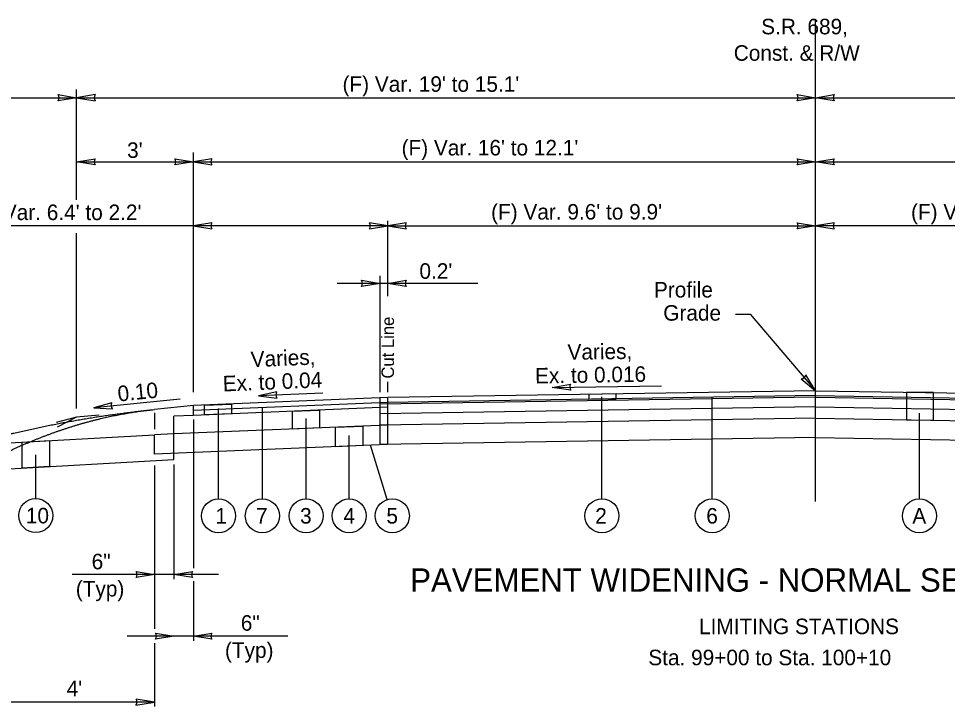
# Model space of a CAD drawing. Extents: x -219 to 803, y -225 to 180.
# Drawn here: x 42.76 to 90.53, y 54.8 to 90.2 of the extents above; entities that cross this region are included whole.
import ezdxf

# ---------------------------------------------------------------- set-up
doc = ezdxf.new("R2010")
doc.units = 0
for name, color, linetype in [('Level 16', 7, 'Continuous'), ('SH_Data', 7, 'Continuous'), ('XS_X_Pavt', 7, 'Continuous')]:
    doc.layers.add(name, color=color, linetype=linetype)

msp = doc.modelspace()

# ---------------------------------------------------------------- linework, layer by layer
at = {"layer": 'Level 16'}
for p, q in [((83.75, 65.34), (83.75, 90.095)), ((45.75, 80.865), (45.75, 86.556)), ((29.75, 86.128), (45.75, 86.128)), ((44.8, 86.286), (45.75, 86.128)), ((45.75, 86.128), (44.803, 85.97)), ((46.7, 86.286), (45.75, 86.128)), ((45.75, 86.128), (83.75, 86.128)), ((45.75, 86.128), (46.697, 85.97)), ((82.8, 86.286), (83.75, 86.128)), ((83.75, 86.128), (82.803, 85.97)), ((83.75, 86.128), (84.697, 86.286)), ((83.75, 86.128), (121.75, 86.128)), ((84.7, 85.97), (83.75, 86.128)), ((84.697, 86.286), (84.697, 86.286)), ((44.803, 85.97), (44.803, 85.97)), ((46.697, 85.97), (46.697, 85.97)), ((82.803, 85.97), (82.803, 85.97)), ((51.75, 70.976), (51.75, 83.314)), ((45.75, 82.828), (46.696, 82.986)), ((46.7, 82.67), (45.75, 82.828)), ((45.75, 82.828), (51.75, 82.828)), ((46.696, 82.986), (46.696, 82.986)), ((50.8, 82.986), (51.75, 82.828)), ((51.75, 82.828), (50.803, 82.67)), ((50.803, 82.67), (50.803, 82.67)), ((52.7, 82.986), (51.75, 82.828)), ((51.75, 82.828), (83.75, 82.828)), ((51.75, 82.828), (52.697, 82.67)), ((52.697, 82.67), (52.697, 82.67)), ((82.8, 82.986), (83.75, 82.828)), ((83.75, 82.828), (82.803, 82.67)), ((82.803, 82.67), (82.803, 82.67)), ((83.75, 82.828), (84.697, 82.986)), ((83.75, 82.828), (115.75, 82.828)), ((84.7, 82.67), (83.75, 82.828)), ((84.697, 82.986), (84.697, 82.986)), ((61.75, 75.906), (61.75, 79.792)), ((51.75, 79.528), (39.562, 79.528)), ((52.7, 79.686), (51.75, 79.528)), ((51.75, 79.528), (52.697, 79.37)), ((61.75, 79.528), (51.75, 79.528)), ((52.697, 79.37), (52.697, 79.37)), ((60.8, 79.37), (61.75, 79.528)), ((61.75, 79.528), (60.804, 79.686)), ((60.804, 79.686), (60.804, 79.686)), ((62.7, 79.686), (61.75, 79.528)), ((61.75, 79.528), (83.75, 79.528)), ((61.75, 79.528), (62.697, 79.37)), ((62.697, 79.37), (62.697, 79.37)), ((82.8, 79.686), (83.75, 79.528)), ((83.75, 79.528), (82.803, 79.37)), ((82.803, 79.37), (82.803, 79.37)), ((84.7, 79.686), (83.75, 79.528)), ((105.75, 79.528), (83.75, 79.528)), ((83.75, 79.528), (84.697, 79.37)), ((84.697, 79.37), (84.697, 79.37)), ((45.75, 70.13), (45.75, 79.157)), ((61.35, 70.976), (61.35, 76.956)), ((61.35, 76.573), (59.144, 76.573)), ((60.4, 76.731), (61.35, 76.573)), ((61.35, 76.573), (60.403, 76.415)), ((61.75, 76.573), (61.35, 76.573)), ((61.75, 76.573), (62.696, 76.731)), ((66.374, 76.573), (61.75, 76.573)), ((62.7, 76.415), (61.75, 76.573)), ((62.696, 76.731), (62.696, 76.731)), ((60.403, 76.415), (60.403, 76.415)), ((79.625, 74.992), (80.389, 74.992)), ((80.389, 74.992), (83.75, 71.043)), ((83.009, 71.657), (83.75, 71.043)), ((83.75, 71.043), (83.25, 71.862)), ((83.25, 71.862), (83.25, 71.862)), ((61.75, 70.976), (61.75, 71.51)), ((70.206, 71.205), (71.148, 71.386)), ((70.206, 71.205), (75.817, 71.295)), ((71.159, 71.07), (70.206, 71.205)), ((71.148, 71.386), (71.148, 71.386)), ((61.75, 70.694), (51.75, 70.278)), ((56.035, 70.986), (55.092, 70.789)), ((58.408, 70.927), (55.092, 70.789)), ((55.092, 70.789), (56.045, 70.67)), ((83.75, 71.043), (61.75, 70.694)), ((61.75, 70.445), (61.75, 70.694)), ((83.751, 70.793), (61.751, 70.445)), ((72.763, 65.483), (72.763, 70.73)), ((78.435, 65.483), (78.435, 70.709)), ((83.749, 70.793), (105.749, 70.445)), ((83.75, 71.043), (105.75, 70.694)), ((51.07, 70.618), (46.629, 70.173)), ((47.558, 70.425), (46.629, 70.173)), ((51.75, 70.278), (49.75, 70.078)), ((51.75, 69.778), (51.75, 70.278)), ((61.752, 70.445), (51.752, 70.028)), ((56.045, 70.67), (56.045, 70.67)), ((61.75, 68.278), (61.75, 70.445)), ((46.9, 69.793), (45.75, 69.678)), ((46.629, 70.173), (47.586, 70.11)), ((47.586, 70.11), (47.586, 70.11)), ((49.75, 69.903), (49.75, 69.06)), ((51.75, 69.778), (50.75, 69.736)), ((50.75, 68.82), (50.75, 69.736)), ((61.746, 70.194), (51.75, 69.778)), ((53.047, 65.483), (53.047, 70.124)), ((55.298, 65.483), (55.298, 70.176)), ((89.085, 65.483), (89.085, 69.896)), ((45.75, 69.678), (44.703, 69.416)), ((45.75, 69.678), (44.746, 69.176)), ((61.74, 69.277), (50.75, 68.82)), ((51.755, 69.564), (51.755, 61.915)), ((57.549, 65.483), (57.549, 69.614)), ((50.75, 68.82), (49.75, 68.778)), ((50.75, 67.82), (50.75, 68.82)), ((39.957, 68.23), (49.75, 68.778)), ((49.75, 67.778), (49.75, 68.778)), ((59.765, 65.483), (59.765, 68.74)), ((61.735, 68.277), (49.75, 67.778)), ((50.75, 67.499), (50.75, 67.832)), ((61.724, 65.444), (60.859, 68.241)), ((33.106, 66.51), (50.75, 67.499)), ((43.645, 65.494), (43.645, 67.747)), ((49.75, 67.199), (49.75, 58.788)), ((50.755, 67.257), (50.755, 61.347)), ((48.805, 61.748), (49.755, 61.59)), ((50.755, 61.59), (51.702, 61.748)), ((51.702, 61.748), (51.702, 61.748)), ((49.755, 61.59), (45.512, 61.59)), ((49.755, 61.59), (48.809, 61.432)), ((48.809, 61.432), (48.809, 61.432)), ((50.755, 61.59), (49.755, 61.59)), ((53.047, 61.59), (50.755, 61.59)), ((51.705, 61.432), (50.755, 61.59)), ((51.755, 61.251), (51.755, 58.169)), ((50.755, 58.412), (48.353, 58.412)), ((49.806, 58.57), (50.755, 58.412)), ((50.755, 58.412), (49.809, 58.254)), ((51.755, 58.412), (50.755, 58.412)), ((51.755, 58.412), (52.702, 58.57)), ((52.705, 58.254), (51.755, 58.412)), ((56.611, 58.412), (51.755, 58.412)), ((52.702, 58.57), (52.702, 58.57)), ((49.75, 58.048), (49.75, 54.797)), ((49.809, 58.254), (49.809, 58.254)), ((49.75, 55.015), (41.75, 55.015)), ((48.8, 54.857), (49.75, 55.015)), ((49.75, 55.015), (48.804, 55.173)), ((48.804, 55.173), (48.804, 55.173))]:
    msp.add_line(p, q, dxfattribs=at)
for points in [[(73.492, 70.88), (72.092, 70.858), (72.092, 70.608), (73.492, 70.63)], [(89.814, 69.53), (89.814, 70.947), (88.414, 70.969), (88.414, 69.552)], [(52.316, 69.802), (52.316, 70.302), (53.716, 70.36), (53.716, 69.86)], [(56.843, 69.073), (56.843, 69.99), (58.243, 70.049), (58.243, 69.132)], [(59.068, 68.166), (59.068, 69.166), (60.468, 69.224), (60.468, 68.224)], [(42.953, 67.062), (42.953, 68.397), (44.353, 68.476), (44.353, 67.14)]]:
    msp.add_lwpolyline(points, close=True, dxfattribs=at)
for centre in [(43.645, 64.619), (53.047, 64.608), (55.298, 64.608), (57.549, 64.608), (59.765, 64.608), (61.982, 64.608), (72.763, 64.608), (78.435, 64.608), (89.085, 64.608)]:
    msp.add_circle(centre, 0.875, dxfattribs=at)
for centre, start, end in [((44.561, 86.126), 327.1412, 33.822), ((46.939, 86.126), 146.178, 212.8588), ((82.561, 86.126), 327.1412, 33.822), ((84.939, 86.13), 147.1412, 213.822), ((46.939, 82.83), 147.1412, 213.822), ((50.561, 82.826), 327.1412, 33.822), ((52.939, 82.826), 146.178, 212.8588), ((82.561, 82.826), 327.1412, 33.822), ((84.939, 82.83), 147.1412, 213.822), ((52.939, 79.526), 146.178, 212.8588), ((60.561, 79.53), 326.178, 32.8588), ((62.939, 79.526), 146.178, 212.8588), ((82.561, 79.526), 327.1412, 33.822), ((84.939, 79.526), 146.178, 212.8588), ((60.161, 76.571), 327.1412, 33.822), ((62.939, 76.575), 147.1412, 213.822), ((82.974, 71.943), 277.0534, 343.7342), ((71.394, 71.235), 148.5155, 215.1963), ((56.28, 70.836), 148.5639, 215.2447), ((47.812, 70.29), 151.8882, 218.569), ((48.566, 61.588), 327.1412, 33.822), ((51.944, 61.592), 147.1412, 213.822), ((49.567, 58.41), 327.1412, 33.822), ((52.944, 58.414), 147.1412, 213.822), ((48.561, 55.017), 326.178, 32.8588)]:
    msp.add_arc(centre, 0.288, start, end, dxfattribs=at)
for points in [[(41.75, 68.678), (41.904, 68.716), (42.058, 68.754), (42.212, 68.791), (42.365, 68.828), (42.519, 68.865), (42.673, 68.901), (42.827, 68.936), (42.981, 68.971), (43.135, 69.006), (43.288, 69.04), (43.442, 69.074), (43.596, 69.108), (43.75, 69.14), (43.904, 69.173), (44.058, 69.205), (44.212, 69.237), (44.365, 69.268), (44.519, 69.298), (44.673, 69.329), (44.827, 69.358), (44.981, 69.388), (45.135, 69.417), (45.288, 69.445), (45.442, 69.473), (45.596, 69.501), (45.75, 69.528), (45.904, 69.555), (46.058, 69.581), (46.212, 69.607), (46.365, 69.632), (46.519, 69.657), (46.673, 69.682), (46.827, 69.706), (46.981, 69.729), (47.135, 69.752), (47.288, 69.775), (47.442, 69.797), (47.596, 69.819), (47.75, 69.84), (47.904, 69.861), (48.058, 69.882), (48.212, 69.902), (48.365, 69.922), (48.519, 69.941), (48.673, 69.959), (48.827, 69.978), (48.981, 69.995), (49.135, 70.013), (49.288, 70.03), (49.442, 70.046), (49.596, 70.062), (49.75, 70.078)], [(41.75, 67.678), (41.904, 67.754), (42.058, 67.829), (42.212, 67.903), (42.365, 67.976), (42.519, 68.048), (42.673, 68.118), (42.827, 68.187), (42.981, 68.255), (43.135, 68.322), (43.288, 68.388), (43.442, 68.453), (43.596, 68.516), (43.75, 68.578), (43.904, 68.639), (44.058, 68.699), (44.212, 68.757), (44.365, 68.815), (44.519, 68.871), (44.673, 68.926), (44.827, 68.98), (44.981, 69.032), (45.135, 69.084), (45.288, 69.134), (45.442, 69.183), (45.596, 69.231), (45.75, 69.278), (45.904, 69.324), (46.058, 69.368), (46.212, 69.411), (46.365, 69.453), (46.519, 69.494), (46.673, 69.534), (46.827, 69.572), (46.981, 69.609), (47.135, 69.645), (47.288, 69.68), (47.442, 69.714), (47.596, 69.747), (47.75, 69.778), (47.904, 69.808), (48.058, 69.837), (48.212, 69.865), (48.365, 69.892), (48.519, 69.917), (48.673, 69.941), (48.827, 69.964), (48.981, 69.986), (49.135, 70.007), (49.288, 70.026), (49.442, 70.045), (49.596, 70.062), (49.75, 70.078)]]:
    msp.add_spline(points, degree=3, dxfattribs=at)
at = {"layer": 'SH_Data'}
for p, q in [((83.717, 70.709), (61.35, 70.355)), ((83.783, 70.709), (106.15, 70.355)), ((61.35, 68.278), (61.35, 70.678)), ((83.75, 70.209), (61.35, 69.855)), ((83.75, 70.209), (106.15, 69.855)), ((83.75, 69.627), (61.35, 69.272)), ((83.75, 69.627), (106.15, 69.272)), ((83.75, 68.632), (61.35, 68.278)), ((83.75, 68.632), (106.15, 68.278))]:
    msp.add_line(p, q, dxfattribs=at)
at = {"layer": 'XS_X_Pavt'}
for points in [[(45.743, 86.129), (45.747, 86.127)], [(45.745, 86.13), (45.747, 86.127)], [(45.755, 86.13), (45.753, 86.127)], [(45.757, 86.129), (45.753, 86.127)], [(83.743, 86.129), (83.747, 86.127)], [(83.745, 86.13), (83.747, 86.127)], [(83.755, 86.126), (83.753, 86.128)], [(83.757, 86.126), (83.753, 86.128)], [(45.755, 82.826), (45.752, 82.828)], [(45.757, 82.826), (45.753, 82.828)], [(51.743, 82.829), (51.747, 82.827)], [(51.745, 82.83), (51.747, 82.827)], [(51.755, 82.83), (51.753, 82.827)], [(51.757, 82.829), (51.753, 82.827)], [(83.743, 82.829), (83.747, 82.827)], [(83.745, 82.83), (83.747, 82.827)], [(83.755, 82.826), (83.753, 82.828)], [(83.757, 82.826), (83.753, 82.828)], [(51.755, 79.53), (51.753, 79.527)], [(51.757, 79.529), (51.753, 79.527)], [(61.743, 79.526), (61.747, 79.528)], [(61.745, 79.526), (61.748, 79.528)], [(61.755, 79.53), (61.753, 79.527)], [(61.757, 79.529), (61.753, 79.527)], [(83.743, 79.529), (83.747, 79.527)], [(83.745, 79.53), (83.747, 79.527)], [(83.755, 79.53), (83.753, 79.527)], [(83.757, 79.529), (83.753, 79.527)], [(61.343, 76.574), (61.347, 76.572)], [(61.345, 76.575), (61.347, 76.572)], [(61.755, 76.571), (61.752, 76.573)], [(61.757, 76.572), (61.753, 76.573)], [(70.211, 71.203), (70.209, 71.206)], [(70.213, 71.204), (70.209, 71.206)], [(55.097, 70.791), (55.095, 70.788)], [(55.099, 70.79), (55.095, 70.788)], [(83.744, 71.047), (83.748, 71.045)], [(83.745, 71.045), (83.749, 71.045)], [(46.634, 70.176), (46.631, 70.173)], [(46.636, 70.175), (46.632, 70.173)], [(49.748, 61.591), (49.752, 61.589)], [(49.75, 61.592), (49.753, 61.589)], [(50.76, 61.588), (50.758, 61.59)], [(50.762, 61.588), (50.758, 61.59)], [(50.748, 58.414), (50.752, 58.412)], [(50.75, 58.414), (50.753, 58.412)], [(51.761, 58.41), (51.758, 58.413)], [(51.762, 58.411), (51.759, 58.413)], [(49.743, 55.014), (49.747, 55.016)], [(49.745, 55.013), (49.748, 55.016)]]:
    msp.add_lwpolyline(points, dxfattribs=at)

# ---------------------------------------------------------------- texts
at = {"layer": 'Level 16'}
for s, height, p in [('S.R. 689,', 0.8, (80.951, 89.389)), ('Const. & R/W', 0.8, (79.54, 88.029)), ("(F) Var. 19' to 15.1'", 0.8, (59.421, 86.43)), ("3'", 0.8, (48.344, 83.028)), ("(F) Var. 16' to 12.1'", 0.8, (62.458, 83.155)), ("(F) Var. 6.4' to 2.2'", 0.8, (40.29, 79.828)), ("(F) Var. 9.6' to 9.9'", 0.8, (67.061, 79.855)), ("(F) Var. 9.9' to 9.8'", 0.8, (88.655, 79.855)), ("0.2'", 0.8, (63.376, 76.806)), ('Profile', 0.8, (75.436, 75.843)), ('Grade', 0.8, (75.914, 74.652)), ('10', 0.8, (43.138, 64.219)), ('1', 0.8, (52.88, 64.208)), ('7', 0.8, (54.973, 64.208)), ('3', 0.8, (57.24, 64.208)), ('4', 0.8, (59.469, 64.208)), ('5', 0.8, (61.677, 64.208)), ('2', 0.8, (72.416, 64.208)), ('6', 0.8, (78.127, 64.208)), ('A', 0.8, (88.724, 64.208)), ('6"', 0.8, (46.521, 61.855)), ('PAVEMENT WIDENING - NORMAL SECTION', 1.2, (62.901, 60.702)), ('(Typ)', 0.8, (45.705, 60.455)), ('6"', 0.8, (54.191, 58.694)), ('LIMITING STATIONS', 0.8, (77.753, 58.516)), ('(Typ)', 0.8, (53.376, 57.294)), ('Sta. 99+00 to Sta. 100+10', 0.8, (75.145, 56.916)), ("4'", 0.8, (45.236, 55.323))]:
    msp.add_text(s, height=height, dxfattribs=at).set_placement(p)
for s, height, rotation, p in [('Cut Line', 0.64, 90, (62.067, 71.67)), ('Varies,', 0.8, 2.3859, (54.715, 72.257)), ('Varies,', 0.8, 0.9172, (70.997, 72.633)), ('Ex. to 0.016', 0.8, 0.9172, (69.328, 71.416)), ('Ex. to 0.04', 0.8, 2.3859, (53.279, 71.006)), ('0.10', 0.8, 5.7102, (47.896, 70.487))]:
    msp.add_text(s, height=height, rotation=rotation, dxfattribs=at).set_placement(p)

doc.saveas('drawing.dxf')
